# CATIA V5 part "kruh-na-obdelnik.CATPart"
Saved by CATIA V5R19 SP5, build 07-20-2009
Part number: Part2
Bounding box of the stored display mesh (mm): x 0 to 50, y -30 to 30, z -30 to 30
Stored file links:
  H:\Dokumenty\CATIA\diskuze_catia\kruh-na-obdelnik.CATPart
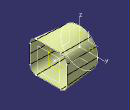
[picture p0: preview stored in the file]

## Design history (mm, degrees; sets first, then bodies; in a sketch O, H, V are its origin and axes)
AxisSystem1: origin (0, 0, 0), X (1, 0, 0), Y (0, 1, 0), Z (0, 0, 1)
Set1
  Plane1: type Offset, RefPlane YZ plane of AxisSystem1, Offset 50
  Sketch1 on Plane1, origin (50, 0, 0), H (0, 1, 0), V (0, 0, 1)
    line L1 (30, 15) -> (30, -15)
    line L2 (20, -25) -> (-20, -25)
    line L3 (-30, -15) -> (-30, 15)
    line L4 (-20, 25) -> (20, 25)
    arc A1 centre (20, 15) radius 10 from (30, 15) to (20, 25) ccw
    arc A2 centre (-20, 15) radius 10 from (-30, 15) to (-20, 25) cw
    arc A3 centre (-20, -15) radius 10 from (-20, -25) to (-30, -15) cw
    arc A4 centre (20, -15) radius 10 from (30, -15) to (20, -25) cw
    distance L2 L4 = 50
    distance L1 L3 = 60
    radius A1 = 10
    radius A2 = 10 {= Sketch1.radius(A1)}
    radius A3 = 10 {= Sketch1.radius(A1)}
    radius A4 = 10 {= Sketch1.radius(A1)}
    vertical: L1 V, L3 V
    horizontal: L2 H, L4 H
    equidistance: L1 L3 O, L2 L4 O
    perpendicularity: L1 L2
    tangency: A1 L1, A1 L4, A2 L3, A2 L4, A3 L2, A3 L3, A4 L1, A4 L2
  Sweep1: type Segment, GuideCrv (Sketch2; Sketch1), Length1 0, Length2 0
Body1 (main body)
  Sketch2 on YZ plane of AxisSystem1, origin (0, 0, 0), H (0, 1, 0), V (0, 0, 1)
    circle A1 centre (0, 0) radius 30
    radius A1 = 30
